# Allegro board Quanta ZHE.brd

Outline 188 x 108 mm; copper layers: TOP, SGND, IN1, SVCC, IN2, IN3, SGND1, BOTTOM. Coordinates in mm from the lower left corner of the outline.
Outline path: 0,9.5 arc(0.29,10.21) 1,10.5 9,10.5 arc(9.71,10.79) 10,11.5 10,12 12.5,12 arc(13.21,12.29) 13.5,13 13.5,87 arc(13.65,87.35) 14,87.5 arc(14.35,87.65) 14.5,88 14.5,91.5 arc(14.35,91.85) 14,92 arc(13.65,92.15) 13.5,92.5 13.5,96 arc(13.79,96.71) 14.5,97 15.5,97 arc(16.21,96.71) 16.5,96 16.5,94.5 arc(16.65,94.15) 17,94 20.5,94 arc(20.85,94.15) 21,94.5 21,107 arc(21.29,107.71) 22,108 23.8,108 arc(24.15,107.85) 24.3,107.5 24.3,107.3 arc(24.45,106.95) 24.8,106.8 30.2,106.8 arc(30.55,106.95) 30.7,107.3 30.7,107.5 arc(30.85,107.85) 31.2,108 42.5,108 arc(44.46,107.4) 45.74,105.81 arc(45.93,105.59) 46.21,105.5 47.05,105.5 arc(47.4,105.65) 47.55,106 47.55,108 50.2,108 50.7,107.5 50.7,102.93 49.5,102.93 49.5,101.03 50.7,101.03 50.7,96.48 arc(51.2,95.98) 51.7,96.48 64.3,96.48 arc(64.8,95.98) 65.3,96.48 65.3,101.03 66.5,101.03 66.5,102.93 65.3,102.93 65.3,107.5 65.8,108 68.45,108 68.95,107.5 68.95,106 arc(69.1,105.65) 69.45,105.5 73.95,105.5 74.45,105 74.45,96.15 arc(74.9,95.65) 75.44,96.05 87.16,96.05 arc(87.7,95.65) 88.15,96.15 88.15,105 88.65,105.5 95.3,105.5 95.7,105.1 95.7,95.87 arc(96.14,95.29) 96.82,95.57 108.28,95.57 arc(108.96,95.29) 109.4,95.87 109.4,105.1 109.8,105.5 111.8,105.5 arc(112.15,105.65) 112.3,106 112.3,107.5 112.8,108 115.2,108 115.6,107.6 115.6,100.1 arc(116.15,99.5) 116.79,100 129.81,100 arc(130.45,99.5) 131,100.1 131,107.6 131.4,108 133.5,108 arc(133.85,107.85) 134,107.5 134,106 arc(134.15,105.65) 134.5,105.5 136,105.5 arc(136.35,105.35) 136.5,105 136.5,87 arc(136.79,86.29) 137.5,86 145.5,86 arc(145.85,85.85) 146,85.5 arc(146.15,85.15) 146.5,85 175,85 arc(175.71,84.71) 176,84 176,77.5 arc(176.29,76.79) 177,76.5 184,76.5 arc(186.12,75.62) 187,73.5 187,67.8 186.55,67.35 176.3,67.35 arc(175.81,66.85) 176.3,66.35 176.3,54.55 arc(175.81,54.05) 176.3,53.55 185,53.55 185.5,53.05 185.5,52 arc(185.55,51.78) 185.7,51.6 186.2,51.1 186.2,48.3 185.7,47.8 180.35,47.8 180.35,48.65 arc(179.55,49.45) 178.75,48.65 178.75,47.8 176.05,47.8 arc(175.45,47.25) 175.95,46.61 175.95,41.69 arc(175.45,41.05) 176.05,40.5 185.7,40.5 186.2,40 186.2,34.52 arc(186.35,34.17) 186.7,34.02 187.5,34.02 188,33.52 188,4.5 arc(186.97,2.03) 184.5,1 126.62,1 arc(124.65,1.61) 123.36,3.23 arc(122.63,4.15) 121.5,4.5 43.15,4.5 arc(41.74,3.91) 41.15,2.5 41.15,1 arc(40.86,0.29) 40.15,0 1,0 arc(0.29,0.29) 0,1 0,9.5

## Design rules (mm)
net group W10-T13B: nets EMMC_RCOMP RSET
net group W12-T13B: nets RREF SDREG
net group W15-T13B: nets MEM_CH0_RCOMP MEM_CH1_RCOMP
net group DFP-S4(5: nets M_A_CLK0 M_A_CLK0# M_A_CLK1 M_A_CLK1# M_A_DQSN0 M_A_DQSN1 M_A_DQSN2 M_A_DQSN3 M_A_DQSN4 M_A_DQSN5 M_A_DQSN6 M_A_DQSN7 M_A_DQSN8 M_A_DQSP0 M_A_DQSP1 M_A_DQSP2 M_A_DQSP3 M_A_DQSP4 M_A_DQSP5 M_A_DQSP6 M_A_DQSP7 M_A_DQSP8
net group DFP-S4W8(6: nets M_B_CLK0 M_B_CLK0# M_B_DQSN0 M_B_DQSN1 M_B_DQSN2 M_B_DQSN3 M_B_DQSN4 M_B_DQSN5 M_B_DQSN6 M_B_DQSN7 M_B_DQSP0 M_B_DQSP1 M_B_DQSP2 M_B_DQSP3 M_B_DQSP4 M_B_DQSP5 M_B_DQSP6 M_B_DQSP7
net group DFP-S5(4: nets CLK_PCIE_LANN CLK_PCIE_LANP CLK_PCIE_WLANN CLK_PCIE_WLANN_NGFF CLK_PCIE_WLANP CLK_PCIE_WLANP_NGFF EDP_AUXN EDP_AUXN_C EDP_AUXP EDP_AUXP_C EDP_RCOMP_N EDP_RCOMP_P EDP_TXN0 EDP_TXN0_C EDP_TXN1 EDP_TXN1_C EDP_TXN2 EDP_TXN2_C EDP_TXN3 EDP_TXN3_C EDP_TXP0 EDP_TXP0_C EDP_TXP1 EDP_TXP1_C EDP_TXP2 EDP_TXP2_C EDP_TXP3 EDP_TXP3_C GPU_CLK#_C GPU_CLK_C GPU_D0#_C GPU_D0_C GPU_D1#_C GPU_D1_C GPU_D2#_C GPU_D2_C INT_HDMICLK+ INT_HDMICLK- INT_HDMITX0N INT_HDMITX0P INT_HDMITX1N INT_HDMITX1P INT_HDMITX2N INT_HDMITX2P PCIE_RCOMPN PCIE_RCOMPP PCIE_RXN2_LAN PCIE_RXN2_LAN_C PCIE_RXN3_WLAN PCIE_RXN3_WLAN_NGFF PCIE_RXP2_LAN PCIE_RXP2_LAN_C PCIE_RXP3_WLAN PCIE_RXP3_WLAN_NGFF PCIE_TXN2_LAN PCIE_TXN2_LAN_C PCIE_TXN3_WLAN PCIE_TXN3_WLAN_C PCIE_TXN3_WLAN_NGFF PCIE_TXP2_LAN PCIE_TXP2_LAN_C PCIE_TXP3_WLAN PCIE_TXP3_WLAN_C PCIE_TXP3_WLAN_NGFF SATA_RXN0 SATA_RXN0_CN SATA_RXN0_HDD#_IC SATA_RXN_1ST_HDD#_C_RD SATA_RXP0 SATA_RXP0_CN SATA_RXP0_HDD_IC SATA_RXP_1ST_HDD_C_RD SATA_TXN0 SATA_TXN0_CN SATA_TXN0_HDD#_IC SATA_TXN_1ST_HDD#_C_RD SATA_TXP0 SATA_TXP0_CN SATA_TXP0_HDD_IC SATA_TXP_1ST_HDD_C_RD USB2.0_CONN3N USB2.0_CONN3P USB3_1_RXN USB3_1_RXP USB3_1_TXN USB3_1_TXP USB30_RX0+_R USB30_RX0-_R USB30_RX0N USB30_RX0P USB30_TX0+_C USB30_TX0+_R USB30_TX0-_C USB30_TX0-_R USB30_TX0N USB30_TX0P USB31_RX1+_R USB31_RX1-_R USB31_TX1+_R USB31_TX1-_R USB31_TX1N_C USB31_TX1P_C USB_BT_N USB_BT_P USB_CAR7_N USB_CAR7_P USB_CAR_N_R USB_CAR_P_R USB_CCD6_N_R USB_CCD6_P_R USB_TS5_N_R USB_TS5_P_R USBP0+_R USBP0-_R USBP0N USBP0P USBP1+_R USBP1-_R USBP1N USBP1P USBP3_C+ USBP3_C- USBP4N USBP4P USBP6_CCDN USBP6_CCDP USBP_TOUCHN USBP_TOUCHP
net group DFP-S6.5(5: nets MDI_0+ MDI_0- MDI_1+ MDI_1- MDI_2+ MDI_2- MDI_3+ MDI_3-
net group DFP-S6.5(5: nets LAN_MX0+ LAN_MX0- LAN_MX1+ LAN_MX1- LAN_MX2+ LAN_MX2- LAN_MX3+ LAN_MX3-
net group DFP-S15(12: nets TX0_HDMI+ TX0_HDMI- TX1_HDMI+ TX1_HDMI- TX2_HDMI+ TX2_HDMI- TXC_HDMI+ TXC_HDMI-
net group GND: nets GND
net group W5.5(3.5: nets 2ND_MBCLK 2ND_MBDATA ACZ_SDIN AZ_CODEC_BITCLK AZ_CODEC_RST# AZ_CODEC_SDIN0 AZ_CODEC_SDOUT AZ_CODEC_SYNC BEEP_1 BITCLK BL_PWM_DIM CLK_24M_DEBUG CLK_24M_DEBUG_C CLK_PCI_EC CLK_SCLK CLK_SDATA CLKRUN# DMIC_CLK DMIC_CLK_C DMIC_CLK_R DMIC_DAT DMIC_DAT_R EMMC_CLK EMMC_CMD EMMC_DATA_0 EMMC_DATA_1 EMMC_DATA_2 EMMC_DATA_3 EMMC_DATA_4 EMMC_DATA_5 EMMC_DATA_6 EMMC_DATA_7 EMMC_RCLK EMMC_RCLK_R FAN1_RPM G_MBCLK_R G_MBDATA_R H_CPU_SVIDCLK H_CPU_SVIDDAT H_PROCHOT# HDA_BCLK_R HDA_RST#_R HDA_SDO_R HDA_SYNC_R HDMI_DDCCLK_SW HDMI_DDCDATA_SW HDMI_SCLK HDMI_SDATA I2C_4_SCL_R I2C_4_SDA_R I2C_TP_SCL_R I2C_TP_SDA_R IOAC_RST# LAD0_C LAD1_C LAD2_C LAD3_C LAN_MCT0 LAN_MCT1 LAN_MCT2 LAN_MCT3 LANCT3 LFRAME#_C LPC_CLKOUT0 LPC_CLKOUT1 LPC_CLKRUN#_R LPC_LAD0 LPC_LAD0_R LPC_LAD1 LPC_LAD1_R LPC_LAD2 LPC_LAD2_R LPC_LAD3 LPC_LAD3_R LPC_LFRAME# LPC_LFRAME#_R M_A_DQ0 M_A_DQ1 M_A_DQ2 M_A_DQ3 M_A_DQ4 M_A_DQ5 M_A_DQ6 M_A_DQ7 M_A_DQ8 M_A_DQ9 M_A_DQ10 M_A_DQ11 M_A_DQ12 M_A_DQ13 M_A_DQ14 M_A_DQ15 M_A_DQ16 M_A_DQ17 M_A_DQ18 M_A_DQ19 M_A_DQ20 M_A_DQ21 M_A_DQ22 M_A_DQ23 M_A_DQ24 M_A_DQ25 M_A_DQ26 M_A_DQ27 M_A_DQ28 M_A_DQ29 M_A_DQ30 M_A_DQ31 M_A_DQ32 M_A_DQ33 M_A_DQ34 M_A_DQ35 M_A_DQ36 M_A_DQ37 M_A_DQ38 M_A_DQ39 M_A_DQ40 M_A_DQ41 M_A_DQ42 M_A_DQ43 M_A_DQ44 M_A_DQ45 M_A_DQ46 M_A_DQ47 M_A_DQ48 M_A_DQ49 M_A_DQ50 M_A_DQ51 M_A_DQ52 M_A_DQ53 M_A_DQ54 M_A_DQ55 M_A_DQ56 M_A_DQ57 M_A_DQ58 M_A_DQ59 M_A_DQ60 M_A_DQ61 M_A_DQ62 M_A_DQ63 M_A_DRAMRST# M_B_DRAMRST# MA_DRAMRST# MB_DRAMRST# MBCLK MBCLK_R MBDATA MBDATA_R PCBEEP PCBEEP_EC PCH_BKLTCTL PCH_BRIGHT PCH_SPI_CLK PCH_SPI_CLK_EC PCH_SPI_IO2 PCH_SPI_IO2_R PCH_SPI_IO3 PCH_SPI_IO3_R PCH_SPI_SI PCH_SPI_SI_EC PCH_SPI_SI_R PCH_SPI_SO PCH_SPI_SO_EC PCH_SPI_SO_R PCH_SUSPWRDNACK PERSTB PLTRST# PLTRST#_2 PMU_RSTBTN# PMU_SUSCLK PROCHOT_EC RTC_X1 RTC_X2 SD_CD# SD_CD#_R SD_CLK SD_CLK_R SD_CMD SD_CMD_R SD_D0 SD_D1 SD_D2 SD_D3 SD_DATA0_R SD_DATA1_R SD_DATA2_R SD_DATA3_R SD_WP SD_WP_R SMB_SOC_CLK SMB_SOC_DAT SOC_RSMRST# SOC_SERIRQ SOC_SERIRQ_R SPI_CLK_A SPI_CS0#_UR_ME SPI_WP# SPKR SUSB# SUSC# SVID_ALERT#_R SVID_CLK#_R SVID_DAT#_R THERMTRIP# THRMTRIP#_R TPCLK TPDATA VCCGI_SENSE VCCGISS_SENSE VNN_SENSE VNNSS_SENSE VR_SVID_ALERT#_VCORE XTAL1 XTAL2 XTAL192_IN XTAL192_OUT
net group W6-T13B: nets CNVI_WT_RCOMP MDSI_RCOMP PCIE_CLK_RCOMP USBCOMP
net group W8(5: nets M_A_A0 M_A_A1 M_A_A2 M_A_A3 M_A_A4 M_A_A5 M_A_A6 M_A_A7 M_A_A8 M_A_A9 M_A_A10 M_A_A11 M_A_A12 M_A_A13 M_A_ACT# M_A_BA#0 M_A_BA#1 M_A_BG#0 M_A_BG#1 M_A_CAS# M_A_CKE0 M_A_CKE1 M_A_CS#0 M_A_CS#1 M_A_ODT0_DIMM M_A_ODT1_DIMM M_A_RAS# M_A_WE# M_B_A0 M_B_A1 M_B_A2 M_B_A3 M_B_A4 M_B_A5 M_B_A6 M_B_A7 M_B_A8 M_B_A9 M_B_A10 M_B_A11 M_B_A12 M_B_A13 M_B_A14 M_B_A15 M_B_A16 M_B_BA#0 M_B_BA#1 M_B_BG#0 M_B_BG#1 M_B_BG#1_1 M_B_BG#1_2 M_B_BG#1_3 M_B_BG#1_4 M_B_CKE0 M_B_CS#0 M_B_DQ0 M_B_DQ1 M_B_DQ2 M_B_DQ3 M_B_DQ4 M_B_DQ5 M_B_DQ6 M_B_DQ7 M_B_DQ8 M_B_DQ9 M_B_DQ10 M_B_DQ11 M_B_DQ12 M_B_DQ13 M_B_DQ14 M_B_DQ15 M_B_DQ16 M_B_DQ17 M_B_DQ18 M_B_DQ19 M_B_DQ20 M_B_DQ21 M_B_DQ22 M_B_DQ23 M_B_DQ24 M_B_DQ25 M_B_DQ26 M_B_DQ27 M_B_DQ28 M_B_DQ29 M_B_DQ30 M_B_DQ31 M_B_DQ32 M_B_DQ33 M_B_DQ34 M_B_DQ35 M_B_DQ36 M_B_DQ37 M_B_DQ38 M_B_DQ39 M_B_DQ40 M_B_DQ41 M_B_DQ42 M_B_DQ43 M_B_DQ44 M_B_DQ45 M_B_DQ46 M_B_DQ47 M_B_DQ48 M_B_DQ49 M_B_DQ50 M_B_DQ51 M_B_DQ52 M_B_DQ53 M_B_DQ54 M_B_DQ55 M_B_DQ56 M_B_DQ57 M_B_DQ58 M_B_DQ59 M_B_DQ60 M_B_DQ61 M_B_DQ62 M_B_DQ63 M_B_ODT0_MD
net group W10-T123B: nets +3V_HDMI DVDD_IO TPM_VDD VDDI_DSC
net group W12-T123B: nets +3V_EC +3VPCU_EC +3VPCU_ECPLL +A3VPCU VSTBY_FSPI
net group W15-T123B: nets +SMDDR_VREF_DQ1_M1 +VREF_CA_CPU +VREFDQ_SB_M3 CCD_PWR M0_VREF_DQ M1_VREF_CA VCC_SPI VREF_CA_DIMM0
net group W20-T13B: nets CODEC_VREF HP-L2 HP-L3 HP-L4 HP-R2 HP-R3 HP-R4 INT_AMIC-VREFO LINE1-L LINE1-R LINE1-VREFO-L LINE1-VREFO-R MIC2-VREFO
net group W20-T123B: nets 1.8V_LDO +1.2V +1.2VSUS +1.05V +1.5V +1.5VA +1.8V +1.8V_EMMC +1.8V_S5 +1.24V_S5 +3V +3V_EMMC +3V_LDO_EC +3V_RTC +3V_RTC_1 +3V_S5 +3VPCU +5V +5V_S5 +5VA +5VPCU +VCCIOA +VCCRAM_1P05 +VCCRAM_1P05_FHV0 +VCCRAM_1P05_FHV1 +VCCRAM_1P05_FUSE +VDD1_1P8 +VDD2_1P24_AUD_ISH +VDD2_1P24_DSI_CSI +VDD2_1P24_GLML +VDD2_1P24_MPHY +VDD2_1P24_PLL +VDD2_1P24_USB2 +VDD2_1P24_VNNAON +VDDQ HDMI_5V RTC_RST# RTC_TEST# TOUCH_SCREEN_PWR VCCRTC_2 VCCRTC_3 VCCRTC_4 VRTC_3P3
net group W30-T123B: nets +5V_FAN1
net group W40-T13B: nets L_SPK+ L_SPK+_CN L_SPK- L_SPK-_CN R_SPK+ R_SPK+_CN R_SPK- R_SPK-_CN RING2_R SLEEVE_R
net group W40-T123B: nets +3V_MINI1_VDD +5V_KB +5V_PVDD +AZA_VDD +VDDQ_VTT +VIN_BLIGHT CARD_3V3 DVDD LANVCC RING2 SLEEVE VDDREG/VDD33 WLAN_VDD
net group W50-T123B: nets +TPVDD_1
net group W60-T123B: nets +LCDVCC_1 LCDVCC REGOUT VDD10
net group W80-T123B: nets +5V_HDD1 USBPWR1 USBPWR2 USBPWR3

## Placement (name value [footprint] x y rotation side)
C1  *0.01u/50V_4  [C0402]  46.9 101.14 270 top
C2  *0.1u/16V_4  [C0402]  70.64 100.63 0 top
C3  1000p/3KV_1808  [CC1808]  41.05 96.57 0 top
C4  *4.7u/6.3V_6  [C0603]  30 95.81 180 top
C5  0.01u/50V_4  [C0402]  35.59 95.55 90 top
C6  0.1u/16V_4  [C0402]  30.51 94.41 0 top
C7  0.1u/16V_4  [C0402]  112.55 94.28 90 top
C8  *10p/50V_4  [C0402]  124.62 94.28 90 top
C9  *10p/50V_4  [C0402]  125.64 94.28 90 top
C10  0.1u/16V_4  [C0402]  85.73 93.34 0 top
C11  470p/50V_4  [C0402]  88.86 92.73 90 top
C12  0.1u/25V_4  [C0402]  114.71 92.51 0 top
C13  0.1u/16V_4  [C0402]  26.32 92.25 0 top
C14  0.1u/16V_4  [C0402]  26.32 90.98 0 top
C15  0.1u/16V_4  [C0402]  103.51 90.73 180 top
C16  1u/6.3V_4  [C0402]  92.74 88.95 90 top
C17  3.3P/50V_4  [C0402]  123.35 88.7 0 top
C18  0.1u/16V_4  [C0402]  33.81 87.17 180 top
C19  *4.7u/6.3V_6  [C0603]  33.81 85.77 0 top
C20  22u/6.3V_6  [C0603]  107.73 85.65 0 top
C21  12p/50V_4  [C0402]  29.88 84.89 270 top
C22  12p/50V_4  [C0402]  31.4 84.89 270 top
C23  10p/50V_4  [C0402]  26.32 84.63 0 top
C24  10p/50V_4  [C0402]  28.23 84.89 0 top
C25  0.1u/16V_4  [C0402]  102.27 83.87 270 top
C26  0.1u/16V_4  [C0402]  103.28 83.87 270 top
C27  *1u/6.3V_4  [C0402]  79.79 82.85 90 top
C28  *1u/6.3V_4  [C0402]  81.57 82.22 90 top
C29  1u/6.3V_4  [C0402]  82.58 82.22 90 top
C30  0.1u/16V_4  [C0402]  83.6 82.22 270 top
C31  *1u/6.3V_4  [C0402]  84.61 82.22 90 top
C32  1u/6.3V_4  [C0402]  85.63 82.22 90 top
C33  1u/6.3V_4  [C0402]  86.65 82.22 90 top
C34  0.1u/16V_4  [C0402]  168.82 81.96 90 top
C35  33p/50V_4  [C0402]  169.83 81.96 270 top
C36  0.01u/25V_4  [C0402]  170.85 81.96 270 top
C37  10u/6.3V_6  [C0603]  161.58 81.84 180 top
C38  *47u/6.3V_8  [C0805]  88.35 81.81 90 top
C39  1u/6.3V_4  [C0402]  114.08 78.66 180 top
C40  0.1u/50V_6  [C0603]  172.63 80.39 0 top
C41  *47u/6.3V_8  [C0805]  78.52 80.31 90 top
C42  1000p/50V_4  [C0402]  165.89 80.19 180 top
C43  1000p/50V_4  [C0402]  167.67 80.19 180 top
C44  *22u/6.3V_6  [C0603]  80.42 79.81 90 top
C45  22u/6.3V_6  [C0603]  81.95 79.81 90 top
C46  22u/6.3V_6  [C0603]  83.47 79.81 90 top
C47  *22u/6.3V_6  [C0603]  85 79.81 90 top
C48  *22u/6.3V_6  [C0603]  86.52 79.81 90 top
C49  1u/6.3V_4  [C0402]  69.12 79.68 90 top
C50  *10p/50V_4  [C0402]  165.89 79.17 0 top
C51  *10p/50V_4  [C0402]  167.67 79.17 0 top
C52  0.1u/50V_6  [C0603]  172.63 78.94 0 top
C53  *47u/6.3V_8  [C0805]  89.19 78.92 0 top
C54  0.1u/16V_4  [C0402]  117 78.92 90 top
C55  0.1u/16V_4  [C0402]  118.02 78.92 90 top
C56  0.1u/16V_4  [C0402]  120.05 78.92 90 top
C57  0.1u/16V_4  [C0402]  121.06 78.92 90 top
C58  0.1u/25V_4  [C0402]  115.86 78.2 270 top
C59  *1u/6.3V_4  [C0402]  125 78.03 180 top
C60  *1000p/50V_4  [C0402]  31.27 77.98 270 top
C61  *0.1u/16V_4  [C0402]  158.4 77.93 90 top
C62  0.1u/25V_4  [C0402]  29.83 77.57 180 top
C63  *47u/6.3V_8  [C0805]  84.74 77.39 180 top
C64  *4.7u/25V_8  [C0805]  172.24 77.24 180 top
C65  *47u/6.3V_8  [C0805]  89.44 76.88 0 top
C66  *1u/6.3V_4  [C0402]  125 76.88 180 top
C67  22u/6.3V_6  [C0603]  101.63 76.58 0 top
C68  *47u/6.3V_8  [C0805]  81.24 76.48 180 top
C69  0.1u/16V_4  [C0402]  118.78 76.12 90 top
C70  0.1u/16V_4  [C0402]  119.79 76.12 90 top
C71  0.1u/16V_4  [C0402]  121.19 76.12 90 top
C72  0.1u/16V_4  [C0402]  122.21 76.12 90 top
C73  *1u/6.3V_4  [C0402]  125 75.87 180 top
C74  0.01u/50V_4  [C0402]  152.05 75.87 90 top
C75  *AC@1u/6.3V_4  [C0402]  21.11 75.49 0 top
C76  *1u/6.3V_4  [C0402]  153.58 75.49 180 top
C77  *47u/6.3V_8  [C0805]  84.74 75.36 180 top
C78  1000p/50V_4  [C0402]  99.07 75.16 90 top
C79  *47u/6.3V_8  [C0805]  88.93 74.6 0 top
C80  1u/6.3V_4  [C0402]  93.76 74.6 270 top
C81  1u/6.3V_4  [C0402]  101.51 74.47 270 top
C82  0.1u/16V_4  [C0402]  97.34 72.97 270 top
C83  *47u/6.3V_8  [C0805]  84.82 72.85 180 top
C84  0.1u/16V_4  [C0402]  82.2 72.69 0 top
C85  *0.1u/16V_4  [C0402]  89.82 72.69 90 top
C86  1u/6.3V_4  [C0402]  97.77 71.63 180 top
C87  *1u/6.3V_4  [C0402]  99.98 70.66 0 top
C88  1u/6.3V_4  [C0402]  97.77 70.61 180 top
C89  1u/6.3V_4  [C0402]  105.06 69.9 180 top
C90  1u/6.3V_4  [C0402]  97.77 69.59 180 top
C91  1u/6.3V_4  [C0402]  99.57 69.59 0 top
C92  *1u/6.3V_4  [C0402]  105.06 68.88 180 top
C93  22u/6.3V_6  [C0603]  95.89 68.73 90 top
C94  0.1u/16V_4  [C0402]  93.76 68.48 0 top
C95  1u/6.3V_4  [C0402]  97.57 68.58 180 top
C96  1u/6.3V_4  [C0402]  99.35 68.58 0 top
C97  VL@10u/25V_8  [C0805]  164.62 68.27 270 top
C98  VL@10u/25V_8  [C0805]  166.66 68.27 270 top
C99  *22u/6.3V_6  [C0603]  90.33 67.99 90 top
C100  22u/6.3V_6  [C0603]  91.75 67.99 90 top
C101  1u/6.3V_4  [C0402]  89.06 67.74 270 top
C102  1u/6.3V_4  [C0402]  94.32 67.51 0 top
C103  *1u/6.3V_4  [C0402]  101.25 67.61 270 top
C104  47u/6.3V_6  [C0603]  109.25 67.49 90 top
C105  22u/6.3V_6  [C0603]  110.78 67.49 90 top
C106  47u/6.3V_6  [C0603]  112.3 67.49 90 top
C107  1u/6.3V_4  [C0402]  103.56 67.26 180 top
C108  1u/6.3V_4  [C0402]  92.95 67.05 270 top
C109  *1u/6.3V_4  [C0402]  99.6 66.62 90 top
C110  47u/6.3V_8  [C0805]  97.82 66.47 270 top
C111  22u/6.3V_6  [C0603]  95.1 66.11 180 top
C112  *1u/6.3V_4  [C0402]  101.33 65.84 90 top
C113  1u/6.3V_4  [C0402]  89.06 65.45 0 top
C114  1u/6.3V_4  [C0402]  99.98 65.28 0 top
C115  1000p/50V_4  [C0402]  82.58 64.69 180 top
C116  1u/6.3V_4  [C0402]  99.98 64.31 0 top
C117  1u/6.3V_4  [C0402]  109.25 63.93 180 top
C118  1u/6.3V_4  [C0402]  102.65 63.68 90 top
C119  1000p/50V_4  [C0402]  81.19 64.72 270 top
C120  22u/6.3V_6  [C0603]  90.2 63.55 180 top
C121  22u/6.3V_6  [C0603]  96.76 63.4 0 top
C122  1u/6.3V_4  [C0402]  99.22 63.3 180 top
C123  *47u/10V_8  [C0805]  114.46 63.3 0 top
C124  *22u/6.3V_6  [C0603]  111.31 63.07 90 top
C125  1u/6.3V_4  [C0402]  101.33 62.91 270 top
C126  *0.1u/25V_4  [C0402]  46.26 62.41 90 top
C127  RAM@1u/6.3V_4  [C0402]  133.89 62.28 270 top
C128  0.01u/50V_4  [C0402]  137.32 62.28 90 top
C129  2200p/50V_4  [C0402]  138.46 62.28 90 top
C130  0.1u/16V_4  [C0402]  139.61 62.28 90 top
C131  RAM@1u/6.3V_4  [C0402]  143.03 62.28 270 top
C132  RAM@1u/6.3V_4  [C0402]  144.18 62.28 270 top
C133  1u/6.3V_4  [C0402]  95.82 61.92 180 top
C134  1u/6.3V_4  [C0402]  92.92 61.9 90 top
C135  1u/6.3V_4  [C0402]  94.27 61.9 90 top
C136  *1u/6.3V_4  [C0402]  99.22 61.9 180 top
C137  1u/6.3V_4  [C0402]  105.7 61.77 0 top
C138  22u/6.3V_6  [C0603]  109.25 61.54 270 top
C139  1u/6.3V_4  [C0402]  101 61.52 180 top
C140  1u/6.3V_4  [C0402]  107.6 61.26 90 top
C141  22u/6.3V_6  [C0603]  97.44 61.14 90 top
C142  *1u/6.3V_4  [C0402]  87.54 60.5 90 top
C143  1u/6.3V_4  [C0402]  88.55 60.5 90 top
C144  1u/6.3V_4  [C0402]  89.52 60.5 90 top
C145  1u/6.3V_4  [C0402]  100.97 60.5 180 top
C146  1u/6.3V_4  [C0402]  94.52 60.37 0 top
C147  *0.1u/25V_4  [C0402]  49.18 60.25 0 top
C148  1u/6.3V_4  [C0402]  92.92 60.12 270 top
C149  1u/6.3V_4  [C0402]  95.99 59.92 90 top
C150  2.2u/10V_4  [C0402]  99.6 59.74 270 top
C151  22u/6.3V_6  [C0603]  119.41 59.36 90 top
C152  22u/6.3V_6  [C0603]  110.14 58.98 0 top
C153  0.1u/16V_4  [C0402]  163.1 58.6 270 top
C154  0.1u/16V_4  [C0402]  164.12 58.6 270 top
C155  0.1u/16V_4  [C0402]  89.47 58.57 90 top
C156  0.1u/25V_4  [C0402]  60.87 58.47 180 top
C157  RAM@1u/6.3V_4  [C0402]  147.35 58.22 90 top
C158  22u/6.3V_6  [C0603]  77.63 57.88 0 top
C159  1u/6.3V_4  [C0402]  67.04 57.62 90 top
C160  *47u/10V_8  [C0805]  70.9 57.58 180 top
C161  EM@1u/6.3V_4  [C0402]  61 56.79 270 top
C162  EM@0.1u/16V_4  [C0402]  62.01 56.79 90 top
C163  EM@1u/6.3V_4  [C0402]  63.15 56.82 270 top
C164  EM@1u/6.3V_4  [C0402]  64.68 57.2 180 top
C165  22u/6.3V_6  [C0603]  77.63 56.44 0 top
C166  22u/6.3V_6  [C0603]  109.25 56.44 270 top
C167  0.1u/16V_4  [C0402]  102.14 56.06 90 top
C168  EM@1u/6.3V_4  [C0402]  58.53 55.93 0 top
C169  22u/6.3V_6  [C0603]  93.35 55.8 90 top
C170  1u/6.3V_4  [C0402]  166.66 55.8 180 top
C171  *47u/10V_8  [C0805]  70.9 55.55 180 top
C172  *0.1u/16V_4  [C0402]  149 53.39 90 bottom
C173  EM@0.1u/16V_4  [C0402]  64.68 56.06 0 top
C174  *22u/6.3V_6  [C0603]  77.63 54.99 0 top
C175  EM@0.1u/16V_4  [C0402]  59.47 54.79 180 top
C176  22u/6.3V_6  [C0603]  85.12 54.79 0 top
C177  *0.1u/25V_4  [C0402]  166.66 54.28 0 top
C178  EM@0.1u/16V_4  [C0402]  59.47 53.77 180 top
C179  22u/6.3V_6  [C0603]  77.63 53.54 0 top
C180  *47u/10V_8  [C0805]  71.03 52.88 270 top
C181  *47u/10V_8  [C0805]  73.06 52.88 270 top
C182  *47u/10V_8  [C0805]  75.22 52.88 270 top
C183  *1000p/50V_4  [C0402]  170.72 52.75 270 top
C184  EM@0.1u/16V_4  [C0402]  64.55 52.14 0 top
C185  4.7u/6.3V_6  [C0603]  172.75 51.87 180 top
C186  EM@0.1u/16V_4  [C0402]  64.55 51.13 0 top
C187  *0.1u/16V_4  [C0402]  83.85 51.1 180 top
C188  100p/50V_4  [C0402]  170.72 50.85 90 top
C189  0.01u/50V_4  [C0402]  147.61 50.72 0 top
C190  100p/50V_4  [C0402]  176.18 50.6 180 top
C191  22u/6.3V_6  [C0603]  88.69 49.77 90 top
C192  RAM@1u/6.3V_4  [C0402]  147.61 49.58 180 top
C193  1u/6.3V_4  [C0402]  151.04 49.33 270 top
C194  1u/6.3V_4  [C0402]  152.05 49.33 270 top
C195  100p/50V_4  [C0402]  172.37 48.56 180 top
C196  0.047u/25V_4  [C0402]  136.3 48.51 0 top
C197  68p/50V_4  [C0402]  131.48 46.15 0 top
C198  68p/50V_4  [C0402]  131.1 48.13 270 top
C199  RAM@1u/6.3V_4  [C0402]  132.37 48.13 90 top
C200  RAM@1u/6.3V_4  [C0402]  133.64 48.13 90 top
C201  0.047u/25V_4  [C0402]  134.78 48.13 270 top
C202  1u/6.3V_4  [C0402]  152.05 47.55 90 top
C203  1u/6.3V_4  [C0402]  160.56 46.28 180 top
C204  10u/6.3V_6  [C0603]  135.16 46.23 0 top
C205  22u/6.3V_6  [C0603]  90.3 45.52 0 top
C206  1u/6.3V_4  [C0402]  96.27 45.34 90 top
C207  22u/6.3V_6  [C0603]  106.84 45.26 0 top
C208  2.2u/6.3V_4  [C0402]  49.82 44.75 180 top
C209  RAM@1u/6.3V_4  [C0402]  134.14 44.37 270 top
C210  RAM@1u/6.3V_4  [C0402]  135.41 44.37 270 top
C211  RAM@10u/6.3V_4  [C0402_2]  136.68 44.37 90 top
C212  0.1u/16V_4  [C0402]  106.84 43.86 0 top
C213  4.7u/6.3V_6  [C0603]  172.63 43.48 270 top
C214  1u/6.3V_4  [C0402]  150.81 42.49 90 top
C215  1u/6.3V_4  [C0402]  151.95 42.49 90 top
C216  0.1u/16V_4  [C0402]  106.84 42.34 0 top
C217  0.1u/16V_4  [C0402]  33.43 41.71 180 top
C218  4.7u/6.3V_6  [C0603]  158.02 42.47 270 top
C219  0.1u/16V_4  [C0402]  159.93 41.45 90 top
C220  68p/50V_4  [C0402]  160.94 41.45 270 top
C221  0.1u/16V_4  [C0402]  23.02 40.94 0 top
C222  68p/50V_4  [C0402]  147.86 40.44 0 top
C223  1u/6.3V_4  [C0402]  49.82 40.18 0 top
C224  RAM@68p/50V_4  [C0402]  147.86 39.29 0 top
C225  1u/6.3V_4  [C0402]  162.97 39.29 270 top
C226  0.1u/16V_4  [C0402]  40.98 37.01 180 top
C227  100p/50V_4  [C0402]  171.08 37.21 0 top
C228  0.1u/16V_4  [C0402]  40.98 35.99 180 top
C229  0.1u/16V_4  [C0402]  20.61 36.24 270 top
C230  0.01u/50V_4  [C0402]  147.86 34.59 0 top
C231  0.1u/16V_4  [C0402]  20.61 34.47 270 top
C232  RAM@1u/6.3V_4  [C0402]  147.86 33.45 180 top
C233  *10p/50V_4  [C0402]  18.19 33.07 180 top
C234  *0.1u/16V_4  [C0402]  170.85 32.69 270 top
C235  RAM@1u/6.3V_4  [C0402]  147.86 32.31 180 top
C236  1u/6.3V_4  [C0402]  20.23 32.05 180 top
C237  0.1u/25V_4  [C0402]  114.97 30.28 180 top
C238  RAM@1u/6.3V_4  [C0402]  132.49 30.28 90 top
C239  RAM@1u/6.3V_4  [C0402]  133.51 30.28 90 top
C240  RAM@1u/6.3V_4  [C0402]  136.94 30.28 90 top
C241  RAM@10u/6.3V_4  [C0402_2]  138.08 30.28 90 top
C242  RAM@10u/6.3V_4  [C0402_2]  139.48 30.28 90 top
C243  2200p/50V_4  [C0402]  140.75 30.28 270 top
C244  2.2u/6.3V_4  [C0402]  143.16 30.28 90 top
C245  0.1u/16V_4  [C0402]  20.23 29.01 0 top
C246  *10u/6.3V_6  [C0603]  170.21 28.62 180 top
C247  *10u/6.3V_6  [C0603]  176.05 28.5 270 top
C248  *0.1u/16V_4  [C0402]  177.32 28.5 90 top
C249  10u/6.3V_6  [C0603]  98.71 28.37 90 top
C250  10u/6.3V_6  [C0603]  76.36 28.24 90 top
C251  1u/6.3V_4  [C0402]  77.76 28.24 90 top
C252  1u/6.3V_4  [C0402]  79.28 28.24 90 top
C253  10u/6.3V_6  [C0603]  80.8 28.24 90 top
C254  1u/6.3V_4  [C0402]  109.25 28.24 90 top
C255  1u/6.3V_4  [C0402]  55.43 27.99 90 top
C256  10u/6.3V_6  [C0603]  87.54 27.99 90 top
C257  0.1u/16V_4  [C0402]  43.09 27.61 180 top
C258  2.2u/10V_6  [C0603]  113.01 27.81 90 top
C259  10u/6.3V_6  [C0603]  65.56 27.74 0 top
C260  0.1u/16V_4  [C0402]  114.97 27.23 180 top
C261  10u/6.3V_6  [C0603]  43.97 25.45 90 top
C262  2.2u/10V_6  [C0603]  115.35 25.96 180 top
C263  10u/6.3V_4  [C0402_2]  181.64 23.93 180 top
C264  10u/6.3V_4  [C0402_2]  183.42 23.93 180 top
C265  2.2u/6.3V_4  [C0402]  180.12 23.67 90 top
C266  1u/16V_6  [C0603]  173.9 23.44 270 top
C267  10u/6.3V_6  [C0603]  175.42 23.42 270 top
C268  1u/16V_6  [C0603]  176.94 23.42 270 top
C269  10u/6.3V_4  [C0402_2]  172.24 22.02 270 top
C270  0.1u/16V_4  [C0402]  183.42 22.78 180 top
C271  0.1u/16V_4  [C0402]  31.4 22.15 90 top
C272  0.1u/16V_4  [C0402]  173.74 21.64 180 top
C273  2.2u/10V_6  [C0603]  116.62 20.88 270 top
C274  1u/6.3V_4  [C0402]  61.37 20.5 270 top
C275  0.1u/16V_4  [C0402]  115.35 20.37 270 top
C276  10u/6.3V_6  [C0603]  82.84 20.24 90 top
C277  10u/6.3V_6  [C0603]  96.04 20.24 90 top
C278  180p/50V_4  [C0402]  18.32 20.12 90 top
C279  1u/6.3V_4  [C0402]  50.2 20.12 270 top
C280  *0.1u/16V_4  [C0402]  73.82 20.12 270 top
C281  1u/6.3V_4  [C0402]  104.05 20.12 270 top
C282  1u/6.3V_4  [C0402]  94.77 19.99 90 top
C283  1u/6.3V_4  [C0402]  168.82 19.99 180 top
C284  10u/6.3V_4  [C0402_2]  174.78 19.99 90 top
C285  10u/6.3V_6  [C0603]  78.39 19.86 0 top
C286  10u/6.3V_6  [C0603]  112.05 19.73 270 top
C287  10u/6.3V_4  [C0402_2]  184.56 19.1 270 top
C288  0.1u/16V_4  [C0402]  172.37 17.58 90 top
C289  10u/6.3V_4  [C0402_2]  173.51 17.58 90 top
C290  1u/6.3V_4  [C0402]  112.05 17.45 90 top
C291  1u/6.3V_4  [C0402]  113.06 17.45 90 top
C292  1u/6.3V_4  [C0402]  114.08 17.45 90 top
C293  1u/6.3V_4  [C0402]  115.09 17.45 90 top
C294  *1000p/50V_4  [C0402]  186.34 16.43 180 top
C295  0.1u/16V_4  [C0402]  172.37 15.8 270 top
C296  10u/6.3V_4  [C0402_2]  173.51 15.8 270 top
C297  GS@10u/6.3V_6  [C0603]  101 14.78 180 top
C298  *100p/50V_4  [C0402]  34.07 13.64 90 top
C299  *100p/50V_4  [C0402]  35.08 13.64 270 top
C300  1u/6.3V_4  [C0402]  66.96 13.64 270 top
C301  1u/6.3V_4  [C0402]  67.98 13.64 270 top
C302  0.1u/16V_4  [C0402]  180.88 13.26 180 top
C304  *22p/50V_4  [C0402]  100.49 13.13 0 top
C305  10u/6.3V_4  [C0402_2]  173.51 13 90 top
C306  0.1u/16V_4  [C0402]  174.78 13 90 top
C307  0.1u/16V_4  [C0402]  182.4 12.75 90 top
C308  KBL@4.7u/10V_6  [C0603]  121.7 12.24 180 top
C309  10u/6.3V_4  [C0402_2]  180.88 12.11 180 top
C310  *22p/50V_4  [C0402]  178.31 12.09 270 top
C311  10u/6.3V_4  [C0402_2]  179.41 12.09 90 top
C312  4.7u/6.3V_6  [C0603]  171.61 11.99 0 top
C313  0.1u/25V_4  [C0402]  64.29 11.86 90 top
C314  0.1u/16V_4  [C0402]  51.98 11.61 0 top
C315  KBL@0.01u/25V_4  [C0402]  121.57 10.97 180 top
C316  100p/50V_4  [C0402]  182.4 10.97 270 top
C317  0.1u/16V_4  [C0402]  150.15 10.84 0 top
C318  10u/6.3V_6  [C0603]  47.4 10.72 0 top
C319  0.1u/16V_4  [C0402]  51.98 10.64 0 top
C320  10p/50V_4  [C0402]  176.82 10.64 0 top
C321  *GS@33p/50V_4  [C0402]  89.44 8.43 90 top
C322  *GS@33p/50V_4  [C0402]  92.49 8.43 90 top
C323  GS@0.1u/16V_4  [C0402]  96.55 8.43 90 top
C324  *0.1u/16V_4  [C0402]  66.96 8.05 270 top
C325  KBL@2.2u/16V_4  [C0402_2]  124.11 7.42 180 top
C326  1000p/50V_4  [C0402]  163.99 5.64 180 top
C327  1000p/50V_4  [C0402]  165.51 5.26 90 top
C328  1000p/50V_4  [C0402]  167.29 5.26 90 top
C329  1000p/50V_4  [C0402]  169.07 5.26 90 top
C330  100u/6.3V_12  [C1206]  91.62 99.54 90 bottom
C331  470p/50V_4  [C0402]  112.55 94.28 90 bottom
C332  1000p/50V_4  [C0402]  121.19 94.28 90 bottom
C333  220p/50V_4  [C0402]  124.85 94.28 90 bottom
C334  0.1u/16V_4  [C0402]  32.8 91.87 270 bottom
C335  1u/6.3V_4  [C0402]  115.86 91.24 90 bottom
C336  0.1u/16V_4  [C0402]  28.48 90.85 270 bottom
C337  100u/6.3V_12  [C1206]  114.08 90.47 270 bottom
C338  0.1u/16V_4  [C0402]  32.8 89.71 270 bottom
C339  0.1u/16V_4  [C0402]  25.94 89.58 0 bottom
C340  1u/6.3V_4  [C0402]  28.48 89.08 270 bottom
C341  0.1u/16V_4  [C0402]  31.4 87.68 180 bottom
C342  0.1u/16V_4  [C0402]  120.05 87.3 270 bottom
C343  0.1u/16V_4  [C0402]  121.06 87.3 270 bottom
C344  0.01u/50V_4  [C0402]  122.08 87.3 270 bottom
C345  10u/6.3V_6  [C0603]  118.85 86.84 90 bottom
C346  0.1u/16V_4  [C0402]  121.95 85.39 180 bottom
C347  0.1u/16V_4  [C0402]  31.66 85.01 0 bottom
C348  0.01u/50V_4  [C0402]  122.46 83.64 180 bottom
C349  0.01u/50V_4  [C0402]  118.24 83.23 90 bottom
C350  0.1u/16V_4  [C0402]  89.57 83.13 0 bottom
C351  *18P/50V_4  [C0402]  92.23 82.98 270 bottom
C352  *18P/50V_4  [C0402]  93.25 82.98 270 bottom
C353  *33p/50V_4  [C0402]  103.79 82.85 90 bottom
C354  0.1u/16V_4  [C0402]  119.59 82.85 0 bottom
C355  0.1u/16V_4  [C0402]  122.46 82.68 180 bottom
C356  *22u/6.3V_6  [C0603]  81.44 82.47 270 bottom
C357  22u/6.3V_6  [C0603]  82.96 82.47 270 bottom
C358  22u/6.3V_6  [C0603]  84.49 82.47 270 bottom
C359  1u/6.3V_4  [C0402]  85.76 82.22 90 bottom
C360  1u/6.3V_4  [C0402]  86.77 82.22 90 bottom
C361  18p/50V_4  [C0402]  99.6 81.3 180 bottom
C362  18p/50V_4  [C0402]  101.38 81.3 0 bottom
C363  0.1u/16V_4  [C0402]  119.79 81.2 90 bottom
C364  0.1u/16V_4  [C0402]  120.81 81.2 90 bottom
C365  0.01u/50V_4  [C0402]  121.95 81.2 90 bottom
C366  0.1u/16V_4  [C0402]  108.87 80.69 270 bottom
C367  0.1u/16V_4  [C0402]  109.89 80.69 270 bottom
C368  0.1u/16V_4  [C0402]  110.9 80.69 90 bottom
C369  0.1u/16V_4  [C0402]  111.92 80.69 90 bottom
C370  *22u/6.3V_6  [C0603]  80.42 79.81 90 bottom
C371  *22u/6.3V_6  [C0603]  81.95 79.81 90 bottom
C372  22u/6.3V_6  [C0603]  83.47 79.81 90 bottom
C373  *22u/6.3V_6  [C0603]  85 79.81 90 bottom
C374  22u/6.3V_6  [C0603]  86.52 79.81 90 bottom
C375  180p/50V_4  [C0402]  170.85 77.65 0 bottom
C376  180p/50V_4  [C0402]  163.61 77.01 90 bottom
C377  0.1u/16V_4  [C0402]  82.07 76.88 0 bottom
C378  0.1u/16V_4  [C0402]  157.77 76 270 bottom
C379  0.1u/16V_4  [C0402]  158.78 76 270 bottom
C380  0.1u/16V_4  [C0402]  160.43 76 270 bottom
C381  0.1u/16V_4  [C0402]  161.45 76 270 bottom
C382  0.1u/16V_4  [C0402]  156.24 73.84 270 bottom
C383  0.1u/16V_4  [C0402]  157.26 73.84 270 bottom
C384  0.1u/16V_4  [C0402]  159.16 73.84 270 bottom
C385  0.1u/16V_4  [C0402]  160.18 73.84 270 bottom
C386  0.1u/16V_4  [C0402]  162.21 73.84 270 bottom
C387  0.1u/16V_4  [C0402]  163.23 73.84 270 bottom
C388  VL@10u/25V_8  [C0805]  175.93 72.82 270 bottom
C389  VL@1u/25V_4  [C0402]  175.17 70.66 180 bottom
C390  15p/50V_4  [C0402]  115.22 69.26 90 bottom
C391  VL@0.1u/16V_4  [C0402]  171.99 69.26 270 bottom
C392  VL@10u/25V_8  [C0805]  163.86 68.1 270 bottom
C393  VL@10u/25V_8  [C0805]  165.89 68.1 270 bottom
C394  15p/50V_4  [C0402]  115.22 67.36 270 bottom
C395  VL@0.1u/25V_4  [C0402]  167.8 65.71 180 bottom
C396  VL@820p/50V_4  [C0402]  170.21 63.17 270 bottom
C397  RAM@1u/6.3V_4  [C0402]  133.89 62.28 270 bottom
C398  RAM@1u/6.3V_4  [C0402]  135.03 62.28 270 bottom
C399  0.01u/50V_4  [C0402]  136.18 62.28 90 bottom
C400  68p/50V_4  [C0402]  137.19 62.28 90 bottom
C401  RAM@1u/6.3V_4  [C0402]  138.34 62.28 270 bottom
C402  3.3P/50V_4  [C0402]  139.35 62.28 90 bottom
C403  3.3P/50V_4  [C0402]  147.35 60.25 90 bottom
C404  68p/50V_4  [C0402]  148.5 60.25 90 bottom
C405  0.047u/25V_4  [C0402]  149.64 60.25 90 bottom
C406  470p/50V_4  [C0402]  167.93 59.1 90 bottom
C407  0.1u/16V_4  [C0402]  168.94 59.1 90 bottom
C408  0.1u/16V_4  [C0402]  169.96 59.1 90 bottom
C409  RAM@10u/6.3V_4  [C0402_2]  147.35 58.22 90 bottom
C410  0.022u/25V_4  [C0402]  149.64 58.22 270 bottom
C411  100u/6.3V_12  [C1206]  170.21 55.17 270 bottom
C412  *TPM@10u/6.3V_6  [C0603]  36.74 54.02 0 bottom
C413  68p/50V_4  [C0402]  147.61 53.06 0 bottom
C414  RAM@10u/6.3V_4  [C0402_2]  147.61 51.79 180 bottom
C415  1u/6.3V_4  [C0402]  151.04 49.33 270 bottom
C416  *TPM@10p/50V_4  [C0402]  34.83 49.2 0 bottom
C417  *TPM@0.1u/16V_4  [C0402]  44.74 47.57 90 bottom
C418  *TPM@0.1u/16V_4  [C0402]  45.75 47.57 90 bottom
C419  1u/6.3V_4  [C0402]  151.01 47.55 270 bottom
C420  1u/6.3V_4  [C0402]  152.05 47.55 90 bottom
C421  *TPM@0.1u/16V_4  [C0402]  40.55 46.68 90 bottom
C422  *TPM@0.1u/16V_4  [C0402]  41.56 46.68 90 bottom
C423  0.047u/25V_4  [C0402]  147.73 42.59 0 bottom
C424  RAM@10u/6.3V_4  [C0402_2]  150.4 42.59 90 bottom
C425  0.1u/16V_4  [C0402]  147.73 41.58 180 bottom
C426  0.1u/16V_4  [C0402]  38.26 41.07 0 bottom
C427  RAM@1u/6.3V_4  [C0402]  147.73 40.44 180 bottom
C428  0.1u/16V_4  [C0402]  28.23 40.18 90 bottom
C429  0.1u/16V_4  [C0402]  29.24 40.18 90 bottom
C430  RAM@1u/6.3V_4  [C0402]  127.67 39.55 0 bottom
C431  RAM@1u/6.3V_4  [C0402]  147.73 39.29 180 bottom
C432  RAM@1u/6.3V_4  [C0402]  127.67 38.53 0 bottom
C433  RAM@1u/6.3V_4  [C0402]  147.86 34.59 180 bottom
C434  *0.01u/50V_4  [C0402]  20.61 34.34 270 bottom
C435  RAM@1u/6.3V_4  [C0402]  147.86 33.58 180 bottom
C436  RAM@1u/6.3V_4  [C0402]  147.86 32.56 180 bottom
C437  2.2u/10V_6  [C0603]  20.56 32.05 90 bottom
C438  *2.7p/50V_4  [C0402]  168.82 30.78 0 bottom
C439  0.01u/50V_4  [C0402]  136.94 30.28 270 bottom
C440  RAM@10u/6.3V_4  [C0402_2]  138.08 30.28 90 bottom
C441  RAM@10u/6.3V_4  [C0402_2]  139.48 30.28 90 bottom
C442  RAM@10u/6.3V_4  [C0402_2]  143.16 30.28 90 bottom
C443  *180p/50V_4  [C0402]  30.64 29.77 270 bottom
C444  180p/50V_4  [C0402]  34.96 30.28 270 bottom
C445  *0.1u/16V_4  [C0402]  39.28 29.77 90 bottom
C446  *0.1u/16V_4  [C0402]  40.29 29.77 90 bottom
C447  0.01u/50V_4  [C0402]  20.35 29.51 270 bottom
C448  *2.7p/50V_4  [C0402]  168.82 28.75 0 bottom
C449  0.1u/16V_4  [C0402]  125.38 28.24 90 bottom
C450  1u/6.3V_4  [C0402]  126.4 28.24 90 bottom
C451  0.01u/25V_4  [C0402]  134.78 25.7 180 bottom
C452  *2.7p/50V_4  [C0402]  168.82 25.7 0 bottom
C453  0.01u/25V_4  [C0402]  126.12 25.58 180 bottom
C454  10u/6.3V_6  [C0603]  16.81 24.59 0 bottom
C455  0.01u/25V_4  [C0402]  134.78 24.69 180 bottom
C456  0.01u/25V_4  [C0402]  126.12 24.56 180 bottom
C457  0.1u/16V_4  [C0402]  17.05 23.41 180 bottom
C458  0.01u/25V_4  [C0402]  134.78 23.67 180 bottom
C459  0.01u/25V_4  [C0402]  126.12 23.49 180 bottom
C460  0.01u/25V_4  [C0402]  134.78 22.66 180 bottom
C461  0.01u/25V_4  [C0402]  126.12 22.48 180 bottom
C462  4.7u/6.3V_4  [C0402_2]  168.82 22.15 180 bottom
C463  10u/6.3V_6  [C0603]  135.92 20.76 270 bottom
C464  1u/6.3V_4  [C0402]  133 20.62 270 bottom
C465  1u/6.3V_4  [C0402]  134.02 20.62 270 bottom
C466  0.1u/25V_4  [C0402]  168.82 19.99 180 bottom
C467  *2.7p/50V_4  [C0402]  168.82 18.72 0 bottom
C468  *1000p/50V_4  [C0402]  83.6 17.83 0 bottom
C469  0.1u/16V_4  [C0402]  89.19 17.83 180 bottom
C470  0.022u/25V_4  [C0402]  95.92 17.58 180 bottom
C471  2.2u/10V_6  [C0603]  17.18 17.19 180 bottom
C472  2.2u/10V_6  [C0603]  93.63 16.05 180 bottom
C473  0.1u/16V_4  [C0402]  83.6 15.67 0 bottom
C474  0.1u/16V_4  [C0402]  90.71 15.67 90 bottom
C475  180p/50V_4  [C0402]  74.07 15.29 90 bottom
C476  *10p/50V_4  [C0402]  76.11 15.29 270 bottom
C477  180p/50V_4  [C0402]  77.12 15.29 90 bottom
C478  *0.1u/16V_4  [C0402]  80.17 15.29 90 bottom
C479  *0.1u/16V_4  [C0402]  82.2 15.29 90 bottom
C480  0.1u/16V_4  [C0402]  83.6 14.65 0 bottom
C481  *2.7p/50V_4  [C0402]  168.82 14.4 0 bottom
C482  0.22u/16V_4  [C0402]  85.71 13.74 180 bottom
C483  *2.7p/50V_4  [C0402]  168.82 12.37 0 bottom
C484  10u/6.3V_6  [C0603]  50.32 17.68 0 bottom
C485  0.1u/16V_4  [C0402]  51.85 15.67 0 bottom
C487  22u/6.3V_6  [C0603]  47.58 14.4 180 top
C488  *22u/6.3V_6  [C0603]  47.58 12.93 180 top
C542  *0.1u/16V_4  [C0402]  59.6 59.99 0 top
CN1  C128H9-K1909-L  [HDMI-C128H9-K1909-L-19P]  123.3 105.75 0 bottom
CN2  TARA8-9V1394  [UB3-TARA8-9V1394-9P-SMT]  102.55 102.9 0 bottom
CN3  C107Y1-10405-L  [USB-020173MR004S55PZR-4P-R-V]  81.3 100.62 0 bottom
CN4  C100KU-10809-L  [RJ45-C100KU-10809-L-8P]  58 97.83 0 bottom
CN5  CVS540WM1RB-NH  [GS12401-1011-40P-R-NH-SMT]  161.73 82 0 bottom
CN6  2UB3914-000101F  [USB-10355-30002-9P]  183.27 60.45 270 bottom
CN7  *ACES_51619-0180N  [88511-180N-18P-L]  49.54 53.97 270 bottom
CN8  2SJ3108-072111F  [AUDIO-2SJ3108-072111F-6P]  183.5 44.15 270 bottom
CN9  50271-0040N-V01  [50271-0040N-V01-4P-L]  15.6 31.82 90 bottom
CN10  NASE0-S6701-TS40  [NGFF-NASE0-S6701-TS40-KE-SMT]  30.65 24.88 0 bottom
CN11  156-2001902600  [SDCARD-156-2001902600-11P-SMT]  173.3 21.45 270 bottom
CN12  51653-0080N-001  [51653-0080N-001-8P-L]  79.65 9.65 180 bottom
CN13  51653-00401-V01  [51653-00401-V01-4P-L]  119 9.2 180 bottom
CN14  AAA-BAT-046-K03  [BAT-AAA-BAT-046-K03-2P-SMT]  151 8.2 180 bottom
CN15  CVS520EM1RB-NH  [GS12201-1011-9F-20P-L-SMT]  52.1 7.8 180 bottom
CN16  KB_CONN  [50584-0280N-V01-28P-L]  24.9 7.97 180 bottom
CN17  50271-0040N-V01  [50271-0040N-V01-4P-L]  166.17 6.69 180 bottom
CP1  *220p/50V_8P4C  [8P4R]  19.34 13.51 180 top
CP2  *220p/50V_8P4C  [8P4R]  23.4 13.51 180 top
CP3  *220p/50V_8P4C  [8P4R]  27.59 13.51 180 top
CP4  *220p/50V_8P4C  [8P4R]  31.66 13.51 180 top
CP5  *220p/50V_8P4C  [8P4R]  37.75 13.51 180 top
CP6  *220p/50V_8P4C  [8P4R]  41.94 13.51 180 top
D1  *AZ5725-01F.R7G  [ESD-1X0_6-2P]  151.54 79.93 90 top
D2  *AZ5725-01F.R7G  [ESD-1X0_6-2P]  152.56 79.93 90 top
D3  VL@DFLS240-7  [D-2_8X1_78]  171.1 73.33 270 top
D4  *DFLS240-7  [D-2_8X1_78]  173.51 73.33 270 top
D5  1N4148WS  [DSM]  155.38 68.2 90 top
D6  EM@RB500V-40  [DSM]  56.04 54.41 0 top
D7  AZ5725-01F.R7G  [ESD-1X0_6-2P]  169.2 50.34 180 top
D8  RB500V-40  [DSM]  17.69 45.9 180 top
D9  *RB500V-40  [DSM]  17.69 43.87 180 top
D10  *RB500V-40  [DSM]  17.69 42.09 180 top
D11  RB500V-40  [DSM]  17.69 40.31 180 top
D12  *AZ5725-01F.R7G  [ESD-1X0_6-2P]  82.2 38.78 90 top
D13  *AZ5725-01F.R7G  [ESD-1X0_6-2P]  83.73 38.78 90 top
D14  *RB500V-40  [DSM]  17.69 38.53 180 top
D15  AZ5725-01F.R7G  [ESD-1X0_6-2P]  169.2 38.23 180 top
D16  AZ5725-01F.R7G  [ESD-1X0_6-2P]  181.77 37.13 180 top
D17  RB500V-40  [DSM]  16.42 33.2 90 top
D18  RB500V-40  [DSM]  16.42 28.37 90 top
D19  *AZ5725-01F.R7G  [ESD-1X0_6-2P]  89.21 27.81 270 top
D20  *AZ5725-01F.R7G  [ESD-1X0_6-2P]  74.84 27.74 270 top
D21  *RB500V-40  [DSM]  17.56 24.82 180 top
D22  *RB500V-40  [DSM]  17.56 23.04 180 top
D23  *AZ5725-01F.R7G  [ESD-1X0_6-2P]  76.36 20.24 270 top
D24  AZ5725-01F.R7G  [ESD-1X0_6-2P]  16.16 20.12 90 top
D25  *AZ5725-01F.R7G  [ESD-1X0_6-2P]  86.01 20.12 270 top
D26  RB500V-40  [DSM]  167.04 19.73 270 top
D27  *RB500V-40  [DSM]  167.04 15.42 90 top
D28  *VPORT 0603 220K-V05  [R0603]  171.61 10.46 180 top
D29  BAT54CW  [UMT_213-3-1_3]  69.88 8.94 270 top
D30  *VPORT 0603 220K-V05  [R0603]  173.26 7.42 0 top
D31  RB500V-40  [DSM]  141.64 27.95 0 top
D32  RB500V-40  [DSM]  172.24 5.76 180 top
D35  RB500V-40  [DSM]  119.79 90.85 180 bottom
D36  RB500V-40  [DSM]  119.79 89.08 180 bottom
D37  *AZ5725-01F.R7G  [ESD-1X0_6-2P]  154.08 76 90 bottom
D38  *AZ5725-01F.R7G  [ESD-1X0_6-2P]  155.35 76 90 bottom
D39  VL@DFLS240-7  [D-2_8X1_78]  166.4 72.82 90 bottom
D40  TVM0G5R5M220R_22p  [R0402]  28.48 38.15 180 bottom
D41  *VPORT 0603 220K-V05  [R0603]  29.14 35.15 270 bottom
EC1  EGA10402V05AH_0.2p  [R0402]  71.41 99.24 180 top
EC2  *EGA10402V05AH_0.2p  [R0402]  70.9 94.66 180 top
EC3  *EGA10402V05AH_0.2p  [R0402]  70.9 93.39 180 top
EC4  *EGA10402V05AH_0.2p  [R0402]  79.94 93.34 0 top
EC5  EGA10402V05AH_0.2p  [R0402]  122.21 94.28 270 bottom
EC6  *TVM0G5R5M220R_22p  [R0402]  123.3 92.71 270 bottom
ESD2  AZC099-04S.R7G  [SOT23-6-2_8-95-6P]  78.52 91.62 0 bottom
HE1  YB8251ST23  [SOT23_213-3_3-2]  184.82 13 0 top
HOLE1  *HG-C276D98P2  [HG-C276D98P2]  42.5 104.5 0 top
HOLE2  *H-O94X106D94X106N  [H-O94X106D94X106N]  36.35 104.5 90 top
HOLE3  *H-C94D94N  [H-C94D94N]  134.35 103.5 0 top
HOLE4  *H-ZHP-2  [H-ZHP-2]  18.5 89.5 0 top
HOLE5  *HG-ZHP-1  [HG-ZHP-1]  130 89.5 0 top
HOLE6  *HG-C276D98P2  [HG-NHP-1P]  184 73 0 top
HOLE7  h-c126d126n  [H-C126D126N]  126.4 48.56 0 top
HOLE8  *HG-C354D126P2  [HG-ZHP-2]  3 4.5 0 top
HOLE9  *HG-ZHP-1  [HG-ZHP-3]  130 4.5 0 top
HOLE10  *HG-C276D98P2  [HG-C276D98P2]  179 4.5 0 top
HOLE11  *H-O94X106D94X106N  [H-O94X106D94X106N]  185 4.5 0 top
HOLE12  *SPAD-RE79X315NP  [SPAD-RE79X315NP]  14.5 75 180 bottom
HOLE13  -  [H-C276D144P2]  74.33 73.56 180 bottom
HOLE14  *SPAD-RE158X158NP  [SPAD-RE158X158NP]  15.49 55.45 180 bottom
HOLE15  -  [H-C276D138P2]  30.65 53.28 180 bottom
HOLE16  -  [H-C276D144P2]  122.83 52.36 180 bottom
HOLE17  *SPAD-RE178X118NP  [SPAD-RE178X118NP]  15.24 39.8 180 bottom
J1  *JUMP  [JOPEN25X30_S]  69.5 12.88 270 top
JDIM1  D4AR0-26001-1P52  [DDR4-D4AR0-26001-1P52-RVS-SMT]  80.65 24.17 180 bottom
L1  0_5%_4  [R0402]  172.37 49.58 180 top
L2  BLM15AG121SN1D  [R0402]  169.83 48.56 270 top
L3  0_5%_4  [R0402]  172.37 45.39 180 top
L4  BLM15AG121SN1D  [R0402]  23.02 39.93 0 top
L5  BLM15AG121SN1D  [R0402]  171.08 38.23 0 top
L6  HCB2012KF-220T60  [R0805]  173.39 28.37 180 top
L7  BLM15AG121SN1D  [R0402]  41.05 27.99 0 top
L8  BLM15AG121SN1D  [R0402]  45.88 26.34 0 top
L9  *S_6  [S0603]  172.88 19.86 180 top
L10  PBY160808T-600Y-N  [R0603]  170.47 16.94 180 top
L11  MCM2012B900GBE  [FILTER-MCM2012B900GBE-4P]  75.98 88.7 90 bottom
L12  *3.3uH_5x5x1.8  [L5_1X5_2-1_6H]  170.97 74.22 180 bottom
LED1  BL/ORG_19-123/S2BHC-A30/2T  [LED19-123-Y2ST1D-C30-2T-4P]  72.09 89 270 top
LED2  BL/ORG_19-123/S2BHC-A30/2T  [LED19-123-Y2ST1D-C30-2T-4P]  83.42 89 270 top
NOREF  -  []  185.17 28.69 0 top
NOREF#2  -  []  252 -36.4 0 top
NOREF#3  -  [unnamed#2]  36.1 101.01 0 top
NOREF#4  -  [unnamed#2]  15.53 13.38 0 top
NOREF#5  -  [unnamed#2]  174.15 82.98 0 top
NOREF#6  -  []  68.61 -55.2 0 top
NOREF#7  -  [unnamed#2]  36.1 101.01 180 bottom
NOREF#8  -  []  143.9 65.71 180 bottom
NOREF#9  -  []  111.41 12.24 180 bottom
NOREF#10  -  [unnamed#2]  173.06 78.36 180 bottom
NOREF#11  -  [unnamed#2]  15.78 12.75 180 bottom
PC1  0.1u/50V_6  [C0603]  27.59 100.13 90 top
PC2  2200p/50V_4  [C0402]  26.22 100.1 90 top
PC3  22u/6.3V_6  [C0603]  70.64 83.87 270 top
PC4  22u/6.3V_6  [C0603]  72.42 83.87 270 top
PC5  22u/6.3V_6  [C0603]  73.95 83.87 270 top
PC6  22u/6.3V_6  [C0603]  75.47 83.87 270 top
PC7  *10u/6.3V_4  [C0402_2]  76.99 83.74 90 top
PC8  0.1u/25V_4  [C0402]  48.55 81.71 270 top
PC9  0.1u/25V_4  [C0402]  49.56 81.71 270 top
PC10  2200p/50V_4  [C0402]  50.58 81.71 270 top
PC11  0.1u/25V_4  [C0402]  141.76 79.81 270 top
PC12  22u/6.3V_6  [C0603]  70.39 79.68 90 top
PC13  22u/6.3V_6  [C0603]  71.91 79.68 90 top
PC14  22u/6.3V_6  [C0603]  73.44 79.68 90 top
PC15  22u/6.3V_6  [C0603]  74.96 79.68 90 top
PC16  0.1u/25V_4  [C0402]  31.91 74.73 270 top
PC17  2200p/50V_4  [C0402]  32.93 74.73 270 top
PC18  0.1u/25V_4  [C0402]  33.94 74.73 270 top
PC19  2200p/50V_4  [C0402]  143.8 74.34 0 top
PC20  *2200p/50V_4  [C0402]  58.83 73.71 180 top
PC21  *0.1u/25V_4  [C0402]  143.8 73.33 0 top
PC22  1000p/50V_4  [C0402]  18.57 71.42 0 top
PC23  2.2u/10V_4  [C0402]  56.67 70.92 0 top
PC24  22u/6.3V_6  [C0603]  42.45 70.53 0 top
PC25  *10u/6.3V_4  [C0402_2]  46.26 70.41 0 top
PC26  0.1u/50V_6  [C0603]  52.61 69.77 180 top
PC27  0.047u/50V_6  [C0603]  17.69 69.52 0 top
PC28  2.2u/10V_4  [C0402]  31.02 69.52 180 top
PC29  22u/6.3V_6  [C0603]  42.45 69.01 0 top
PC30  22u/6.3V_6  [C0603]  46.26 69.01 180 top
PC31  0.1u/50V_6  [C0603]  36.86 68.76 0 top
PC32  1000p/50V_4  [C0402]  49.94 68.76 180 top
PC33  0.1u/25V_4  [C0402]  31.02 68.38 0 top
PC34  22u/6.3V_6  [C0603]  42.45 67.49 0 top
PC35  22u/6.3V_6  [C0603]  46.26 67.49 180 top
PC36  1000p/50V_4  [C0402]  151.8 67.23 180 top
PC37  *0.1u/16V_4  [C0402]  49.82 66.47 0 top
PC38  1000p/50V_4  [C0402]  151.8 66.22 180 top
PC39  22u/6.3V_6  [C0603]  42.45 65.96 0 top
PC40  22u/6.3V_6  [C0603]  46.26 65.96 180 top
PC41  0.47u/6.3V_4  [C0402]  27.72 64.82 180 top
PC42  0.1u/16V_4  [C0402]  38.13 64.06 180 top
PC43  2.2u/10V_4  [C0402]  38.13 63.04 180 top
PC44  *0.1u/25V_4  [C0402]  31.15 62.15 180 top
PC45  *100p/50V_4  [C0402]  53.88 61.77 270 top
PC46  *0.1u/25V_4  [C0402]  55.02 61.77 270 top
PC47  0.1u/16V_4  [C0402]  29.24 61.39 90 top
PC48  1000p/50V_4  [C0402]  38.51 61.39 90 top
PC49  0.47u/10V_4  [C0402]  27.72 60.25 0 top
PC50  0.1u/16V_4  [C0402]  150.91 57.83 0 top
PC51  *VL@0.1u/25V_4  [C0402]  159.93 56.95 0 top
PC52  *22u/6.3V_6  [C0603]  150.91 56.61 0 top
PC53  22u/6.3V_6  [C0603]  150.91 55.19 0 top
PC54  22u/6.3V_6  [C0603]  150.91 53.77 0 top
PC55  0.1u/25V_4  [C0402]  157 51.23 180 top
PC56  *680p/50V_6  [C0603]  156.75 49.07 90 top
PC57  10p/50V_4  [C0402]  157.13 45.52 0 top
PC58  0.1u/25V_4  [C0402]  161.32 36.12 0 top
PC59  0.1u/25V_4  [C0402]  161.32 35.1 180 top
PC60  *2200p/50V_4  [C0402]  159.93 34.47 90 top
PC61  2200p/50V_4  [C0402]  161.32 34.09 180 top
PC62  10u/25V_8  [C0805]  151.16 33.07 0 top
PC63  *680p/50V_6  [C0603]  163.1 32.56 0 top
PC64  10u/25V_8  [C0805]  152.18 31.04 0 top
PC65  4.7u/10V_6  [C0603]  166.78 30.53 90 top
PC66  *680p/50V_6  [C0603]  152.31 27.48 90 top
PC67  0.1u/25V_4  [C0402]  165.13 27.1 0 top
PC68  0.1u/16V_4  [C0402]  147.48 19.35 270 top
PC69  22u/6.3V_8  [C0805]  149 19.35 270 top
PC70  22u/6.3V_8  [C0805]  151.04 19.35 270 top
PC71  22u/6.3V_8  [C0805]  153.07 19.35 270 top
PC72  22u/6.3V_8  [C0805]  155.1 19.35 270 top
PC73  0.1u/16V_4  [C0402]  164.62 19.1 180 top
PC74  *680p/50V_6  [C0603]  135.29 17.96 180 top
PC75  *22u/6.3V_6  [C0603]  164.62 17.83 180 top
PC76  0.1u/25V_4  [C0402]  141.59 17.2 180 top
PC77  0.1u/25V_4  [C0402]  143.42 17.19 0 top
PC78  0.1u/25V_4  [C0402]  145.19 17.19 0 top
PC79  *22u/6.3V_6  [C0603]  164.62 16.31 180 top
PC80  2200p/50V_4  [C0402]  88.81 16.05 0 top
PC81  10u/6.3V_6  [C0603]  114.21 15.42 0 top
PC82  0.01u/50V_4  [C0402]  140.11 15.29 90 top
PC83  *100p/50V_4  [C0402]  88.81 15.04 0 top
PC84  22u/6.3V_6  [C0603]  164.62 14.78 180 top
PC85  *0.01u/50V_4  [C0402]  123.48 13.89 90 top
PC86  22u/25V_8  [C0805]  88.81 13.51 0 top
PC87  2.2u/10V_6  [C0603]  139.35 13.38 0 top
PC88  4.7u/6.3V_6  [C0603]  111.03 12.62 180 top
PC89  0.1u/50V_6  [C0603]  88.81 11.73 0 top
PC90  *10u/6.3V_6  [C0603]  116.87 11.73 90 top
PC91  0.1u/16V_4  [C0402]  118.14 11.73 90 top
PC92  *0.1u/16V_4  [C0402]  154.59 11.35 270 top
PC93  0.1u/16V_4  [C0402]  155.61 11.35 270 top
PC94  *0.1u/16V_4  [C0402]  156.62 11.35 270 top
PC95  0.047u/50V_6  [C0603]  139.35 10.34 0 top
PC96  1u/25V_4  [C0402]  153.32 9.57 90 top
PC97  1u/25V_4  [C0402]  157.89 9.57 90 top
PC98  0.47u/6.3V_4  [C0402]  115.48 8.94 0 top
PC99  0.47u/25V_6  [C0603]  139.35 8.81 0 top
PC100  *100p/50V_4  [C0402]  150.15 8.81 0 top
PC101  10u/6.3V_6  [C0603]  159.16 8.05 270 top
PC102  10u/6.3V_6  [C0603]  152.13 7.95 270 top
PC103  0.1u/16V_4  [C0402]  153.32 7.8 270 top
PC104  0.1u/16V_4  [C0402]  157.89 7.8 270 top
PC105  0.1u/50V_6  [C0603]  141.76 7.29 0 top
PC106  100p/50V_4  [C0402]  150.15 6.78 0 top
PC107  1000p/50V_4  [C0402]  155.1 6.02 90 top
PC108  1000p/50V_4  [C0402]  156.12 6.02 90 top
PC109  0.1u/50V_6  [C0603]  140.88 5.26 90 top
PC110  0.1u/50V_6  [C0603]  142.4 5.26 270 top
PC111  100p/50V_4  [C0402]  147.48 4.88 270 top
PC112  22u/6.3V_6  [C0603]  67.6 84.63 270 bottom
PC113  22u/6.3V_6  [C0603]  69.12 84.63 270 bottom
PC114  22u/6.3V_6  [C0603]  70.64 83.87 270 bottom
PC115  22u/6.3V_6  [C0603]  72.42 83.87 270 bottom
PC116  22u/6.3V_6  [C0603]  73.95 83.87 270 bottom
PC117  22u/6.3V_6  [C0603]  75.47 83.87 270 bottom
PC118  *680p/50V_6  [C0603]  136.94 83.11 0 bottom
PC119  0.1u/16V_4  [C0402]  111.77 86.79 0 bottom
PC120  10u/25V_8  [C0805]  50.96 81.71 90 bottom
PC121  10u/25V_8  [C0805]  53.12 81.71 90 bottom
PC122  10u/6.3V_6  [C0603]  144.43 81.71 0 bottom
PC123  0.047u/16V_4  [C0402]  146.34 81.58 270 bottom
PC124  *22u/6.3V_6  [C0603]  125.7 80.82 270 bottom
PC125  22u/6.3V_6  [C0603]  127.11 80.82 270 bottom
PC126  *22u/6.3V_6  [C0603]  128.52 80.82 270 bottom
PC127  22u/6.3V_6  [C0603]  129.94 80.82 270 bottom
PC128  22u/6.3V_6  [C0603]  131.35 80.82 270 bottom
PC129  22u/6.3V_6  [C0603]  68.87 79.68 90 bottom
PC130  22u/6.3V_6  [C0603]  70.39 79.68 90 bottom
PC131  22u/6.3V_6  [C0603]  71.91 79.68 90 bottom
PC132  22u/6.3V_6  [C0603]  73.44 79.68 90 bottom
PC133  *10u/6.3V_4  [C0402_2]  74.84 79.68 270 bottom
PC134  *2200p/50V_4  [C0402]  33.81 77.52 0 bottom
PC135  *0.047u/16V_4  [C0402]  149.26 77.27 90 bottom
PC136  0.1u/16V_4  [C0402]  128.3 77.01 90 bottom
PC137  22u/6.3V_6  [C0603]  129.7 77.01 90 bottom
PC138  22u/6.3V_6  [C0603]  131.22 77.01 90 bottom
PC139  *1000p/50V_4  [C0402]  149.26 75.49 90 bottom
PC140  0.1u/50V_6  [C0603]  21.72 75.44 180 bottom
PC141  *0.01u/50V_4  [C0402]  143.8 74.34 0 bottom
PC142  *0.1u/16V_4  [C0402]  135.03 73.96 180 bottom
PC143  *22p/50V_4  [C0402]  139.22 73.96 180 bottom
PC144  10u/25V_8  [C0805]  30.23 73.71 90 bottom
PC145  10u/25V_8  [C0805]  32.21 73.71 90 bottom
PC146  10u/25V_8  [C0805]  143.8 72.82 0 bottom
PC147  0.1u/25V_4  [C0402]  122.51 72.77 90 bottom
PC148  2200p/50V_4  [C0402]  28.35 72.06 180 bottom
PC149  *10u/6.3V_4  [C0402_2]  46.9 72.06 0 bottom
PC150  *68p/50V_4  [C0402]  139.22 71.93 180 bottom
PC151  1u/6.3V_4  [C0402]  139.22 70.92 180 bottom
PC152  0.1u/50V_6  [C0603]  27.97 70.79 180 bottom
PC153  22u/6.3V_6  [C0603]  42.45 70.53 0 bottom
PC154  22u/6.3V_6  [C0603]  46.26 70.53 180 bottom
PC155  0.1u/25V_4  [C0402]  56.55 69.77 270 bottom
PC156  10u/6.3V_6  [C0603]  136.56 69.14 0 bottom
PC157  22u/6.3V_6  [C0603]  42.45 69.01 0 bottom
PC158  22u/6.3V_6  [C0603]  46.26 69.01 180 bottom
PC159  1u/25V_4  [C0402]  153.19 68.88 0 bottom
PC160  0.47u/6.3V_4  [C0402]  62.39 68.25 180 bottom
PC161  *2200p/50V_4  [C0402]  134.14 68.25 270 bottom
PC162  0.01u/50V_4  [C0402]  136.56 67.87 0 bottom
PC163  10u/6.3V_6  [C0603]  148.62 67.87 90 bottom
PC164  *0.1u/16V_4  [C0402]  155.35 67.61 180 bottom
PC165  1000p/50V_4  [C0402]  40.16 67.49 0 bottom
PC166  22u/6.3V_6  [C0603]  42.45 67.49 0 bottom
PC167  22u/6.3V_6  [C0603]  46.26 67.49 180 bottom
PC168  0.1u/16V_4  [C0402]  150.15 67.49 90 bottom
PC169  22u/6.3V_6  [C0603]  128.81 67.36 180 bottom
PC170  0.1u/16V_4  [C0402]  19.51 67.16 270 bottom
PC171  *10u/6.3V_6  [C0603]  22.18 66.98 270 bottom
PC172  10u/6.3V_6  [C0603]  20.73 66.93 270 bottom
PC173  0.1u/16V_4  [C0402]  17 66.83 180 bottom
PC174  0.1u/16V_4  [C0402]  155.35 66.6 180 bottom
PC175  22u/6.3V_6  [C0603]  42.45 65.96 0 bottom
PC176  22u/6.3V_6  [C0603]  46.26 65.96 180 bottom
PC177  1u/6.3V_4  [C0402]  59.47 65.71 270 bottom
PC178  0.1u/16V_4  [C0402]  150.15 65.71 270 bottom
PC179  *0.1u/16V_4  [C0402]  155.35 65.58 180 bottom
PC180  10u/6.3V_6  [C0603]  148.62 65.2 270 bottom
PC181  2.2u/10V_4  [C0402]  49.82 64.44 0 bottom
PC182  0.1u/16V_4  [C0402]  59.85 64.31 180 bottom
PC183  1u/25V_4  [C0402]  153.58 64.18 0 bottom
PC184  0.1u/50V_6  [C0603]  163.1 64.06 180 bottom
PC185  100p/50V_4  [C0402]  55.4 63.04 0 bottom
PC186  *0.1u/50V_6  [C0603]  160.43 62.53 0 bottom
PC187  10u/6.3V_6  [C0603]  163.1 62.53 180 bottom
PC188  1000p/50V_4  [C0402]  49.82 62.03 0 bottom
PC189  220p/50V_4  [C0402]  55.4 62.03 180 bottom
PC190  82p/50V_4  [C0402]  32.67 61.26 90 bottom
PC191  *100p/50V_4  [C0402]  30.64 60.25 270 bottom
PC192  *100p/50V_4  [C0402]  31.66 60.25 270 bottom
PC193  4.7u/6.3V_4  [C0402_2]  19.59 60.32 90 bottom
PC194  *100p/50V_4  [C0402]  55.15 59.74 180 bottom
PC195  330p/50V_4  [C0402]  32.67 59.23 270 bottom
PC196  1u/25V_4  [C0402]  166.28 58.6 180 bottom
PC197  22u/6.3V_6  [C0603]  150.91 56.56 0 bottom
PC198  *22u/6.3V_6  [C0603]  150.91 55.04 0 bottom
PC199  22u/6.3V_6  [C0603]  150.91 53.52 0 bottom
PC200  10u/6.3V_6  [C0603]  163.1 52.12 180 bottom
PC201  4.7u/6.3V_4  [C0402_2]  153.7 47.67 0 bottom
PC202  0.1u/16V_4  [C0402]  153.7 46.53 180 bottom
PC203  1u/10V_4  [C0402]  153.7 45.52 0 bottom
PC204  *33u/25V_D6.3H4.5  [ECAP6_3X6_1-7_2]  164.5 45.39 180 bottom
PC205  0.1u/16V_4  [C0402]  153.7 43.48 180 bottom
PC206  2200p/50V_4  [C0402]  155.35 43.48 90 bottom
PC207  10u/25V_8  [C0805]  157.51 43.23 180 bottom
PC208  10u/25V_8  [C0805]  157.26 41.2 180 bottom
PC209  0.1u/25V_4  [C0402]  153.7 40.44 180 bottom
PC210  10u/25V_8  [C0805]  162.34 36.5 0 bottom
PC211  0.1u/25V_4  [C0402]  153.7 35.61 0 bottom
PC212  0.1u/25V_4  [C0402]  153.7 34.59 0 bottom
PC213  10u/25V_8  [C0805]  162.34 34.47 0 bottom
PC214  0.1u/25V_4  [C0402]  152.18 33.58 0 bottom
PC215  0.1u/16V_4  [C0402]  164.88 33.45 0 bottom
PC216  2200p/50V_4  [C0402]  152.18 32.56 0 bottom
PC217  10p/50V_4  [C0402]  167.04 31.8 0 bottom
PC218  0.1u/16V_4  [C0402]  167.04 29.77 0 bottom
PC219  1u/10V_4  [C0402]  167.04 28.75 180 bottom
PC220  1u/6.3V_4  [C0402]  144.3 27.48 270 bottom
